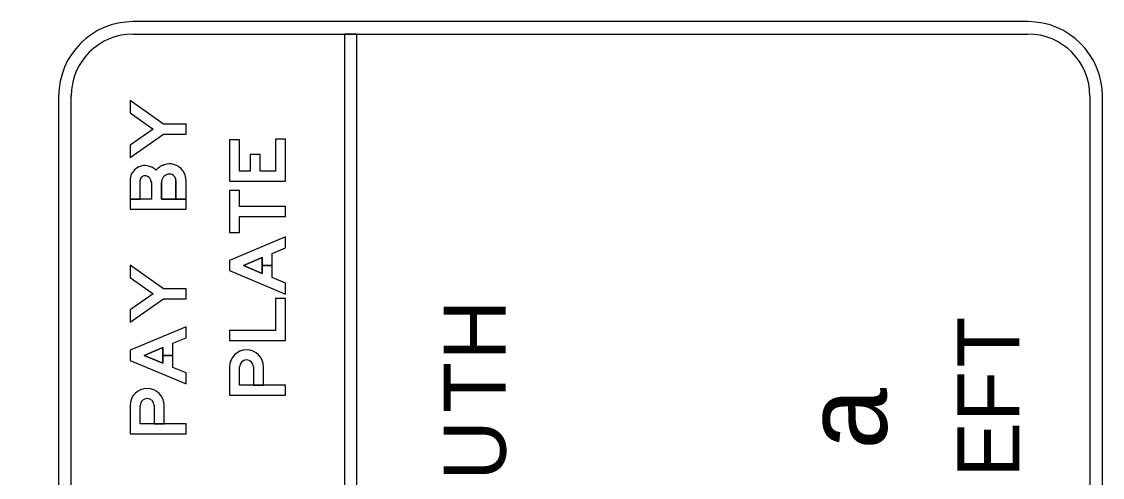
# Model space of a CAD drawing. Extents: x -830008.4 to -829992.7, y 1290284.1 to 1290294.4.
# Drawn here: x -829998.98 to -829998.11, y 1290293.064 to 1290293.43 of the extents above; entities that cross this region are included whole.
import ezdxf

# ---------------------------------------------------------------- set-up
doc = ezdxf.new("R2010")
doc.units = 0
doc.layers.add('1', color=7, linetype='Continuous')
doc.layers.add('SheetBorder_dp', color=7, linetype='Continuous')

msp = doc.modelspace()

# ---------------------------------------------------------------- linework, layer by layer
at = {"layer": '1'}
msp.add_arc((-829995.62331, 1290293.6404), 3.97527, 185.30621, 226.07069, dxfattribs=at)
at = {"layer": 'SheetBorder_dp'}
for p, q in [((-829998.17015, 1290293.43038), (-829998.89015, 1290293.43038)), ((-829998.89015, 1290293.42038), (-829998.17015, 1290293.42038)), ((-829998.71015, 1290293.42038), (-829998.72015, 1290293.42038)), ((-829998.72015, 1290293.42038), (-829998.72015, 1290292.51038)), ((-829998.71015, 1290292.51038), (-829998.71015, 1290293.42038)), ((-829998.95015, 1290293.37038), (-829998.95015, 1290292.56038)), ((-829998.94015, 1290292.56038), (-829998.94015, 1290293.37038)), ((-829998.12015, 1290293.37038), (-829998.12015, 1290292.56048)), ((-829998.11015, 1290292.56048), (-829998.11015, 1290293.37038)), ((-829998.84765, 1290293.27947), (-829998.84765, 1290293.30265)), ((-829998.80455, 1290293.13798), (-829998.80455, 1290293.1526)), ((-829998.80455, 1290293.13798), (-829998.80455, 1290293.1526)), ((-829998.80455, 1290293.13798), (-829998.80455, 1290293.1526)), ((-829998.7852, 1290293.13798), (-829998.7852, 1290293.1526)), ((-829998.88455, 1290293.10698), (-829998.88455, 1290293.1216)), ((-829998.88455, 1290293.10698), (-829998.88455, 1290293.1216)), ((-829998.88455, 1290293.10698), (-829998.88455, 1290293.1216)), ((-829998.8652, 1290293.10698), (-829998.8652, 1290293.1216))]:
    msp.add_line(p, q, dxfattribs=at)
for points in [[(-829998.86588, 1290293.34798), (-829998.89265, 1290293.36688), (-829998.89265, 1290293.35696), (-829998.87419, 1290293.34393), (-829998.89265, 1290293.33089), (-829998.89265, 1290293.32098), (-829998.86588, 1290293.33988), (-829998.84765, 1290293.33988), (-829998.84765, 1290293.34798)], [(-829998.86588, 1290293.34798), (-829998.89265, 1290293.36688), (-829998.89265, 1290293.35696), (-829998.87419, 1290293.34393), (-829998.89265, 1290293.33089), (-829998.89265, 1290293.32098), (-829998.86588, 1290293.33988), (-829998.84765, 1290293.33988), (-829998.84765, 1290293.34798)], [(-829998.86588, 1290293.34798), (-829998.89265, 1290293.36688), (-829998.89265, 1290293.35696), (-829998.87419, 1290293.34393), (-829998.89265, 1290293.33089), (-829998.89265, 1290293.32098), (-829998.86588, 1290293.33988), (-829998.84765, 1290293.33988), (-829998.84765, 1290293.34798)], [(-829998.77575, 1290293.33588), (-829998.77575, 1290293.31023), (-829998.78786, 1290293.31023), (-829998.78786, 1290293.3235), (-829998.79596, 1290293.3235), (-829998.79596, 1290293.31023), (-829998.80455, 1290293.31023), (-829998.80455, 1290293.3352), (-829998.81265, 1290293.3352), (-829998.81265, 1290293.30213), (-829998.76765, 1290293.30213), (-829998.76765, 1290293.33588)], [(-829998.77575, 1290293.33588), (-829998.77575, 1290293.31023), (-829998.78786, 1290293.31023), (-829998.78786, 1290293.3235), (-829998.79596, 1290293.3235), (-829998.79596, 1290293.31023), (-829998.80455, 1290293.31023), (-829998.80455, 1290293.3352), (-829998.81265, 1290293.3352), (-829998.81265, 1290293.30213), (-829998.76765, 1290293.30213), (-829998.76765, 1290293.33588)], [(-829998.77575, 1290293.33588), (-829998.77575, 1290293.31023), (-829998.78786, 1290293.31023), (-829998.78786, 1290293.3235), (-829998.79596, 1290293.3235), (-829998.79596, 1290293.31023), (-829998.80455, 1290293.31023), (-829998.80455, 1290293.3352), (-829998.81265, 1290293.3352), (-829998.81265, 1290293.30213), (-829998.76765, 1290293.30213), (-829998.76765, 1290293.33588)], [(-829998.80455, 1290293.26076), (-829998.80455, 1290293.27358), (-829998.76765, 1290293.27358), (-829998.76765, 1290293.28168), (-829998.80455, 1290293.28168), (-829998.80455, 1290293.29451), (-829998.81265, 1290293.29451), (-829998.81265, 1290293.26076)], [(-829998.80455, 1290293.26076), (-829998.80455, 1290293.27358), (-829998.76765, 1290293.27358), (-829998.76765, 1290293.28168), (-829998.80455, 1290293.28168), (-829998.80455, 1290293.29451), (-829998.81265, 1290293.29451), (-829998.81265, 1290293.26076)], [(-829998.80455, 1290293.26076), (-829998.80455, 1290293.27358), (-829998.76765, 1290293.27358), (-829998.76765, 1290293.28168), (-829998.80455, 1290293.28168), (-829998.80455, 1290293.29451), (-829998.81265, 1290293.29451), (-829998.81265, 1290293.26076)], [(-829998.77823, 1290293.2245), (-829998.77823, 1290293.24395), (-829998.76765, 1290293.24839), (-829998.76765, 1290293.25718), (-829998.81265, 1290293.23828), (-829998.81265, 1290293.23018), (-829998.76765, 1290293.21128), (-829998.76765, 1290293.22006)], [(-829998.78633, 1290293.24055), (-829998.78633, 1290293.23423), (-829998.77823, 1290293.23423), (-829998.77823, 1290293.24395), (-829998.76765, 1290293.24839), (-829998.76765, 1290293.25718), (-829998.81265, 1290293.23828), (-829998.81265, 1290293.23018), (-829998.76765, 1290293.21128), (-829998.76765, 1290293.22006), (-829998.77823, 1290293.2245), (-829998.77823, 1290293.23423), (-829998.78633, 1290293.23423), (-829998.78633, 1290293.2279), (-829998.80138, 1290293.23423)], [(-829998.78633, 1290293.24055), (-829998.78633, 1290293.23423), (-829998.77823, 1290293.23423), (-829998.77823, 1290293.24395), (-829998.76765, 1290293.24839), (-829998.76765, 1290293.25718), (-829998.81265, 1290293.23828), (-829998.81265, 1290293.23018), (-829998.76765, 1290293.21128), (-829998.76765, 1290293.22006), (-829998.77823, 1290293.2245), (-829998.77823, 1290293.23423), (-829998.78633, 1290293.23423), (-829998.78633, 1290293.2279), (-829998.80138, 1290293.23423)], [(-829998.78633, 1290293.24055), (-829998.80138, 1290293.23423), (-829998.78633, 1290293.2279)], [(-829998.86588, 1290293.21557), (-829998.89265, 1290293.23447), (-829998.89265, 1290293.22456), (-829998.87419, 1290293.21152), (-829998.89265, 1290293.19849), (-829998.89265, 1290293.18857), (-829998.86588, 1290293.20747), (-829998.84765, 1290293.20747), (-829998.84765, 1290293.21557)], [(-829998.86588, 1290293.21557), (-829998.89265, 1290293.23447), (-829998.89265, 1290293.22456), (-829998.87419, 1290293.21152), (-829998.89265, 1290293.19849), (-829998.89265, 1290293.18857), (-829998.86588, 1290293.20747), (-829998.84765, 1290293.20747), (-829998.84765, 1290293.21557)], [(-829998.86588, 1290293.21557), (-829998.89265, 1290293.23447), (-829998.89265, 1290293.22456), (-829998.87419, 1290293.21152), (-829998.89265, 1290293.19849), (-829998.89265, 1290293.18857), (-829998.86588, 1290293.20747), (-829998.84765, 1290293.20747), (-829998.84765, 1290293.21557)], [(-829998.76765, 1290293.20769), (-829998.77553, 1290293.20769), (-829998.77553, 1290293.18204), (-829998.81265, 1290293.18204), (-829998.81265, 1290293.17394), (-829998.76765, 1290293.17394)], [(-829998.76765, 1290293.20769), (-829998.77553, 1290293.20769), (-829998.77553, 1290293.18204), (-829998.81265, 1290293.18204), (-829998.81265, 1290293.17394), (-829998.76765, 1290293.17394)], [(-829998.76765, 1290293.20769), (-829998.77553, 1290293.20769), (-829998.77553, 1290293.18204), (-829998.81265, 1290293.18204), (-829998.81265, 1290293.17394), (-829998.76765, 1290293.17394)], [(-829998.85823, 1290293.15223), (-829998.85823, 1290293.17167), (-829998.84765, 1290293.17611), (-829998.84765, 1290293.1849), (-829998.89265, 1290293.166), (-829998.89265, 1290293.1579), (-829998.84765, 1290293.139), (-829998.84765, 1290293.14779)], [(-829998.86633, 1290293.16827), (-829998.86633, 1290293.16195), (-829998.85823, 1290293.16195), (-829998.85823, 1290293.17167), (-829998.84765, 1290293.17611), (-829998.84765, 1290293.1849), (-829998.89265, 1290293.166), (-829998.89265, 1290293.1579), (-829998.84765, 1290293.139), (-829998.84765, 1290293.14779), (-829998.85823, 1290293.15223), (-829998.85823, 1290293.16195), (-829998.86633, 1290293.16195), (-829998.86633, 1290293.15563), (-829998.88138, 1290293.16195)], [(-829998.86633, 1290293.16827), (-829998.86633, 1290293.16195), (-829998.85823, 1290293.16195), (-829998.85823, 1290293.17167), (-829998.84765, 1290293.17611), (-829998.84765, 1290293.1849), (-829998.89265, 1290293.166), (-829998.89265, 1290293.1579), (-829998.84765, 1290293.139), (-829998.84765, 1290293.14779), (-829998.85823, 1290293.15223), (-829998.85823, 1290293.16195), (-829998.86633, 1290293.16195), (-829998.86633, 1290293.15563), (-829998.88138, 1290293.16195)], [(-829998.86633, 1290293.16827), (-829998.88138, 1290293.16195), (-829998.86633, 1290293.15563)]]:
    msp.add_lwpolyline(points, close=True, dxfattribs=at)
for points in [[(-829998.89265, 1290293.30265), (-829998.89265, 1290293.27947), (-829998.84765, 1290293.27947)], [(-829998.89265, 1290293.30265), (-829998.89265, 1290293.28758), (-829998.88455, 1290293.28758), (-829998.88455, 1290293.30265)], [(-829998.89265, 1290293.30265), (-829998.89265, 1290293.28758), (-829998.88455, 1290293.28758), (-829998.88455, 1290293.30265)], [(-829998.87555, 1290293.30091), (-829998.87555, 1290293.28757), (-829998.89265, 1290293.28757), (-829998.89265, 1290293.27947), (-829998.84765, 1290293.27947), (-829998.84765, 1290293.28757)], [(-829998.87555, 1290293.30091), (-829998.87555, 1290293.28757), (-829998.89265, 1290293.28757), (-829998.89265, 1290293.27947), (-829998.84765, 1290293.27947), (-829998.84765, 1290293.28757)], [(-829998.87555, 1290293.30091), (-829998.87555, 1290293.28757), (-829998.88455, 1290293.28757), (-829998.88455, 1290293.30265)], [(-829998.86745, 1290293.30091), (-829998.86745, 1290293.28757), (-829998.85575, 1290293.28757), (-829998.85575, 1290293.30265)], [(-829998.84765, 1290293.28757), (-829998.86745, 1290293.28757), (-829998.86745, 1290293.30091)], [(-829998.84765, 1290293.28757), (-829998.86745, 1290293.28757), (-829998.86745, 1290293.30091)], [(-829998.85575, 1290293.30265), (-829998.85575, 1290293.28758), (-829998.84765, 1290293.28758), (-829998.84765, 1290293.30265)], [(-829998.85575, 1290293.30265), (-829998.85575, 1290293.28758), (-829998.84765, 1290293.28758), (-829998.84765, 1290293.30265)], [(-829998.81265, 1290293.1526), (-829998.81265, 1290293.12988), (-829998.76765, 1290293.12988), (-829998.76765, 1290293.13798), (-829998.7852, 1290293.13798)], [(-829998.81265, 1290293.1526), (-829998.81265, 1290293.12988), (-829998.76765, 1290293.12988), (-829998.76765, 1290293.13798), (-829998.80455, 1290293.13798)], [(-829998.81265, 1290293.1526), (-829998.81265, 1290293.12988), (-829998.76765, 1290293.12988), (-829998.76765, 1290293.13798), (-829998.80455, 1290293.13798)], [(-829998.7933, 1290293.1526), (-829998.7933, 1290293.13798), (-829998.80455, 1290293.13798)], [(-829998.7933, 1290293.1526), (-829998.7933, 1290293.13798), (-829998.7852, 1290293.13798), (-829998.7852, 1290293.1526)], [(-829998.7933, 1290293.1526), (-829998.7933, 1290293.13798), (-829998.7852, 1290293.13798), (-829998.7852, 1290293.1526)], [(-829998.89265, 1290293.1216), (-829998.89265, 1290293.09888), (-829998.84765, 1290293.09888), (-829998.84765, 1290293.10698), (-829998.8652, 1290293.10698)], [(-829998.89265, 1290293.1216), (-829998.89265, 1290293.09888), (-829998.84765, 1290293.09888), (-829998.84765, 1290293.10698), (-829998.88455, 1290293.10698)], [(-829998.89265, 1290293.1216), (-829998.89265, 1290293.09888), (-829998.84765, 1290293.09888), (-829998.84765, 1290293.10698), (-829998.88455, 1290293.10698)], [(-829998.8733, 1290293.1216), (-829998.8733, 1290293.10698), (-829998.88455, 1290293.10698)], [(-829998.8733, 1290293.1216), (-829998.8733, 1290293.10698), (-829998.8652, 1290293.10698), (-829998.8652, 1290293.1216)], [(-829998.8733, 1290293.1216), (-829998.8733, 1290293.10698), (-829998.8652, 1290293.10698), (-829998.8652, 1290293.1216)]]:
    msp.add_lwpolyline(points, dxfattribs=at)
for centre, radius, start, end in [((-829998.89015, 1290293.37038), 0.06, 90, 180), ((-829998.17015, 1290293.37038), 0.06, 360, 90), ((-829998.89015, 1290293.37038), 0.05, 90, 180), ((-829998.17015, 1290293.37038), 0.05, 360, 90)]:
    msp.add_arc(centre, radius, start, end, dxfattribs=at)
for centre, major_axis, ratio, start_param, end_param in [((-829998.88073, 1290293.30265), (-0.01192, 0), 0.999999, 4.459709, 6.283185), ((-829998.88073, 1290293.30265), (-0.01192, 0), 0.999999, 4.459709, 6.283185), ((-829998.88073, 1290293.30265), (-0.01192, 0), 0.999999, 4.459709, 6.283185), ((-829998.86048, 1290293.30091), (-0.01507, 0), 0.999999, 4.965069, 5.558736), ((-829998.86048, 1290293.30091), (-0.01508, 0), 0.999999, 4.965069, 5.558736), ((-829998.86048, 1290293.30091), (-0.01507, 0), 0.999999, 4.965069, 5.558736), ((-829998.86093, 1290293.30265), (-0.01328, 0), 0.999999, 3.141593, 4.965069), ((-829998.86093, 1290293.30265), (-0.01328, 0), 0.999999, 3.141593, 4.965069), ((-829998.86093, 1290293.30265), (-0.01328, 0), 0.999999, 3.141593, 4.965069), ((-829998.88073, 1290293.30265), (-0.00382, 0), 0.999999, 4.459709, 6.283185), ((-829998.88073, 1290293.30265), (-0.00382, 0), 0.999999, 4.459709, 6.283185), ((-829998.88073, 1290293.30265), (-0.00382, 0), 0.999999, 4.459709, 6.283185), ((-829998.88118, 1290293.30091), (-0.00562, 0), 0.999999, 3.141593, 4.459709), ((-829998.88118, 1290293.30091), (-0.00563, 0), 0.999999, 3.141593, 4.459709), ((-829998.88118, 1290293.30091), (-0.00563, 0), 0.999999, 3.141593, 4.459709), ((-829998.88118, 1290293.30091), (-0.01373, 0), 0.999999, 3.95686, 4.459709), ((-829998.88118, 1290293.30091), (-0.01373, 0), 0.999999, 3.95686, 4.459709), ((-829998.88118, 1290293.30091), (-0.01373, 0), 0.999999, 3.95686, 4.459709), ((-829998.86048, 1290293.30091), (-0.00698, 0), 0.999999, 4.965069, 6.283185), ((-829998.86048, 1290293.30091), (-0.00698, 0), 0.999999, 4.965069, 6.283185), ((-829998.86048, 1290293.30091), (-0.00698, 0), 0.999999, 4.965069, 6.283185), ((-829998.86093, 1290293.30265), (-0.00517, 0), 0.999999, 3.141593, 4.965069), ((-829998.86093, 1290293.30265), (-0.00518, 0), 0.999999, 3.141593, 4.965069), ((-829998.86093, 1290293.30265), (-0.00518, 0), 0.999999, 3.141593, 4.965069), ((-829998.79893, 1290293.1526), (-0.01373, 0), 0.999995, 3.141593, 6.283185), ((-829998.79893, 1290293.1526), (-0.01373, 0), 0.999995, 3.141593, 6.283185), ((-829998.79893, 1290293.1526), (-0.01373, 0), 0.999995, 3.141593, 6.283185), ((-829998.79893, 1290293.1526), (-0.00562, 0), 0.999995, 3.141593, 6.283185), ((-829998.79893, 1290293.1526), (-0.00562, 0), 0.999995, 3.141593, 6.283185), ((-829998.79893, 1290293.1526), (-0.00562, 0), 0.999995, 3.141593, 6.283185), ((-829998.87893, 1290293.1216), (-0.01373, 0), 0.999995, 3.141593, 6.283185), ((-829998.87893, 1290293.1216), (-0.01373, 0), 0.999995, 3.141593, 6.283185), ((-829998.87893, 1290293.1216), (-0.01373, 0), 0.999995, 3.141593, 6.283185), ((-829998.87893, 1290293.1216), (-0.00562, 0), 0.999995, 3.141593, 6.283185), ((-829998.87893, 1290293.1216), (-0.00562, 0), 0.999995, 3.141593, 6.283185), ((-829998.87893, 1290293.1216), (-0.00562, 0), 0.999995, 3.141593, 6.283185)]:
    msp.add_ellipse(centre, major_axis=major_axis, ratio=ratio, start_param=start_param, end_param=end_param, dxfattribs=at)

# ---------------------------------------------------------------- texts
for s, height, p in [('H', 0.05, (-829998.59032, 1290293.15815)), ('T', 0.05, (-829998.1769, 1290293.15221)), ('T', 0.05, (-829998.59032, 1290293.1157)), ('F', 0.05, (-829998.1769, 1290293.10861)), ('a', 0.0665, (-829998.28367, 1290293.08621)), ('U', 0.05, (-829998.59032, 1290293.06135)), ('E', 0.05, (-829998.1769, 1290293.06376))]:
    msp.add_text(s, height=height, rotation=90, dxfattribs=at).set_placement(p)

doc.saveas('drawing.dxf')
